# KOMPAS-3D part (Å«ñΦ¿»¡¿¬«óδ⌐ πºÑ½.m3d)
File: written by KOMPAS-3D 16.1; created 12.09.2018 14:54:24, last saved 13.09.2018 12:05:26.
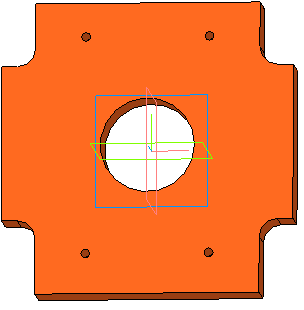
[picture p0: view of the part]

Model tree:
1. Эскиз:2
2. Операция выдавливания:1
     Расстояние 1 = 20
3. Фаска:1
     Угол = 45; Длина 1 = 15; Длина 2 = 15
4. Эскиз:3
5. Вырезать элемент выдавливания:1
     Расстояние 1 = 20
6. Зеркальный массив:1
7. Экземпляр ( 1 )
8. Экземпляр ( 2 )  (with: Вырезать элемент выдавливания:1)
9. Скругление:1
     Радиус = 8
10. Эскиз:4
11. Вырезать элемент выдавливания:2
     Расстояние 1 = 20
12. Зеркальный массив:2  (with: Экземпляр ( 1 ), Экземпляр ( 2 ), Вырезать элемент выдавливания:2)  (labels: Полипропилен  ГОСТ 26996-86)

Expressions: v119/2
